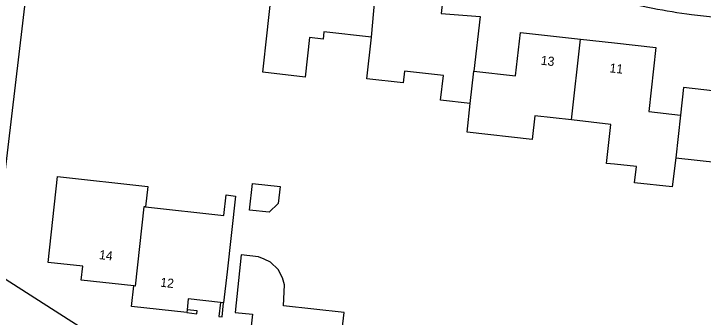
# Model space of a CAD drawing. Extents: x 162398 to 163643, y 386453 to 387397.
# Drawn here: x 162934 to 163009.8, y 386784.8 to 386818.2 of the extents above; entities that cross this region are included whole.
import ezdxf

# ---------------------------------------------------------------- set-up
doc = ezdxf.new("R2010")
doc.units = 0
for name, color, linetype in [('IMGEO_Muur', 7, 'Continuous'), ('IMGEO_Pand', 7, 'Continuous'), ('IMGEO_Pand_nummerreeks', 7, 'Continuous'), ('IMGEO_Voetpad_halfverhard', 7, 'Continuous'), ('IMGEO_Voetpad_open', 7, 'Continuous')]:
    doc.layers.add(name, color=color, linetype=linetype)

msp = doc.modelspace()

# ---------------------------------------------------------------- linework, layer by layer
at = {"layer": 'IMGEO_Muur'}
for points in [[(162956.723, 386786.463), (162956.553, 386784.913), (162956.892, 386784.876), (162957.063, 386786.426)], [(162953.004, 386785.347), (162954.106, 386785.226), (162954.14, 386785.534), (162953.038, 386785.655)]]:
    msp.add_lwpolyline(points, dxfattribs=at)
at = {"layer": 'IMGEO_Pand'}
for points in [[(162973.292, 386815.62), (162974.043, 386823.947)], [(162974.043, 386823.947), (162974.242, 386823.925), (162975.077, 386823.832), (162978.573, 386823.442), (162978.531, 386823.062), (162981.47, 386822.735), (162980.97, 386818.233), (162985.237, 386817.879), (162984.57, 386811.886)], [(162973.292, 386815.62), (162968.082, 386816.199), (162967.993, 386815.401), (162966.514, 386815.566), (162966.034, 386811.238), (162961.367, 386811.756), (162961.845, 386816.085), (162961.994, 386817.437), (162962.693, 386823.773)], [(162984.161, 386808.339), (162980.907, 386808.701), (162981.209, 386811.414), (162976.948, 386811.888), (162976.803, 386810.583), (162972.781, 386811.03), (162973.292, 386815.62)], [(162984.57, 386811.886), (162989.146, 386811.377), (162989.676, 386816.146), (162996.261, 386815.414)], [(162995.272, 386806.521), (162996.261, 386815.414)], [(162996.261, 386815.414), (163000, 386814.998), (163004.553, 386814.492), (163003.769, 386807.446), (163007.27, 386807.057)], [(163019.775, 386812.85), (163012.505, 386813.659), (163012.288, 386811.705), (163012.052, 386809.588), (163007.606, 386810.082), (163007.27, 386807.057)], [(162984.161, 386808.339), (162984.57, 386811.886)], [(162995.272, 386806.521), (162991.268, 386806.966), (162990.979, 386804.374), (162983.809, 386805.171), (162984.161, 386808.339)], [(163006.748, 386802.369), (163006.343, 386799.165), (163002.219, 386799.623), (163002.415, 386801.388), (163000, 386801.656), (162999.149, 386801.751), (162999.626, 386806.037), (162995.272, 386806.521)], [(163007.27, 386807.057), (163006.748, 386802.369)], [(163006.748, 386802.369), (163011.436, 386801.848), (163011.307, 386800.683), (163017.79, 386799.963)], [(162947.188, 386788.278), (162941.411, 386788.914), (162941.579, 386790.443), (162937.765, 386790.862), (162938.803, 386800.302), (162948.722, 386799.212), (162948.475, 386796.963)], [(162959.923, 386796.619), (162960.243, 386799.544), (162963.274, 386799.212), (162963.067, 386797.328), (162962.062, 386796.385), (162959.923, 386796.619)], [(162948.475, 386796.963), (162957.09, 386796.015), (162957.339, 386798.274), (162958.353, 386798.163), (162957.439, 386789.847), (162957.063, 386786.426)], [(162948.475, 386796.963), (162948.312, 386796.981), (162947.352, 386788.26), (162947.188, 386788.278)], [(162970.062, 386783.216), (162970.292, 386785.372), (162963.642, 386786.08), (162963.762, 386788.408), (162963.526, 386789.159), (162963.048, 386790.094), (162962.209, 386790.885), (162961.513, 386791.231), (162960.88, 386791.491), (162958.999, 386791.706), (162958.325, 386785.379), (162960.221, 386785.177), (162959.727, 386780.54), (162959.358, 386777.078), (162963.071, 386776.682), (162962.944, 386775.488)], [(162953.004, 386785.347), (162946.939, 386786.015), (162947.188, 386788.278)], [(162956.723, 386786.463), (162953.169, 386786.853), (162953.038, 386785.655)], [(162957.063, 386786.426), (162956.723, 386786.463)], [(162953.038, 386785.655), (162953.004, 386785.347)]]:
    msp.add_lwpolyline(points, dxfattribs=at)
at = {"layer": 'IMGEO_Voetpad_halfverhard'}
msp.add_lwpolyline([(162939.497, 386855.132), (162935.841, 386824.556), (162935.369, 386820.614), (162931.696, 386789.898)], dxfattribs=at)
at = {"layer": 'IMGEO_Voetpad_open'}
for points in [[(163008.483, 386818.116), (163032.153, 386815.458)], [(162931.696, 386789.898), (162994.075, 386750), (163000, 386746.21), (163010.632, 386739.479), (163010.94, 386739.303), (163011.262, 386739.156), (163011.596, 386739.037), (163011.94, 386738.949), (163012.29, 386738.893), (163012.643, 386738.867), (163012.998, 386738.873), (163013.35, 386738.911), (163013.698, 386738.981), (163014.038, 386739.081), (163014.368, 386739.211), (163014.685, 386739.37), (163014.944, 386739.528)]]:
    msp.add_lwpolyline(points, dxfattribs=at)
msp.add_arc((163017.316, 386886.201), 68.656, 255.39121, 262.60785, dxfattribs=at)

# ---------------------------------------------------------------- texts
at = {"layer": 'IMGEO_Pand_nummerreeks'}
for s, rotation, p in [('13', 353.64835, (162991.875, 386812.601)), ('11', 353.66208, (162999.429, 386811.761)), ('14', 353.72038, (162943.343, 386791.237)), ('12', 353.72038, (162950.065, 386788.206))]:
    msp.add_text(s, height=1, rotation=rotation, dxfattribs=at).set_placement(p)

doc.saveas('drawing.dxf')
